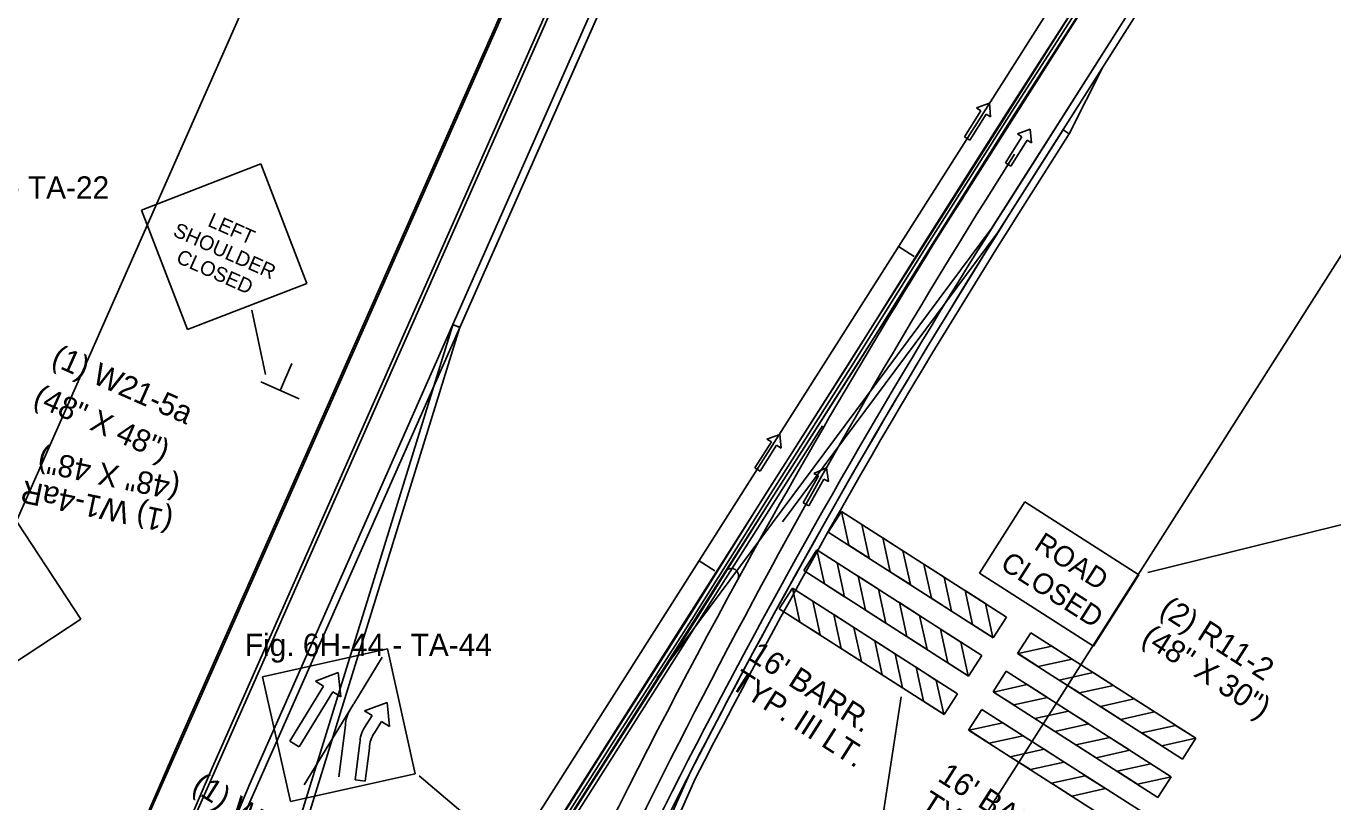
# Model space of a CAD drawing. Extents: x 659657 to 668193, y 633084 to 648639.
# Drawn here: x 661763.9 to 662115.3, y 641655.6 to 641864.1 of the extents above; entities that cross this region are included whole.
import ezdxf

# ---------------------------------------------------------------- set-up
doc = ezdxf.new("R2010")
doc.units = 0
for name, color, linetype in [('R_Border Prem', 7, 'Continuous'), ('R_Draft', 7, 'Continuous'), ('R_MOT_Stage 1A', 7, 'Continuous'), ('R_MOT_Stage 1A_Striping', 7, 'Continuous'), ('R_MOT_Stage 1B', 7, 'Continuous'), ('R_MOT_Stage 1B_Striping', 7, 'Continuous'), ('R_MOT_Stage 1C', 7, 'Continuous'), ('R_MOT_Stage 1C_Striping', 7, 'Continuous'), ('R_MOT_Stage 2', 7, 'Continuous'), ('R_MOT_Stage 2_Striping', 7, 'Continuous'), ('R_MOT_Stage 3_Striping_PPM', 7, 'Continuous'), ('R_MOT_Stage 4_Striping_PPM', 7, 'Continuous'), ('R_MOT_Stage 5_Striping_PPM', 7, 'Continuous'), ('S_EXISTING_ALIGNMENT', 7, 'Continuous'), ('T_Notes', 7, 'Continuous'), ('T_SIGNAL CONTROL CABINET', 7, 'Continuous'), ('TEMP_SIGNAL_HEAD_STAGE 2', 7, 'Continuous'), ('TEMP_SIGNAL_POLES_STAGE 3', 7, 'Continuous'), ('TEXT_TEMP_SIGNAL_POLES_STAGE 2', 7, 'Continuous')]:
    doc.layers.add(name, color=color, linetype=linetype)

msp = doc.modelspace()

# ---------------------------------------------------------------- linework, layer by layer
at = {"layer": 'R_Border Prem'}
msp.add_line((661686.79, 641562.92), (662861.91, 644217.67), dxfattribs=at)
at = {"layer": 'R_Draft'}
for p, q in [((661826.96, 641827.04), (661794.88, 641814.65)), ((661839.35, 641794.96), (661826.96, 641827.04)), ((661807.28, 641782.58), (661794.88, 641814.65)), ((661839.35, 641794.96), (661807.28, 641782.58)), ((661824.57, 641787.78), (661828.28, 641770.48)), ((661832.24, 641766.37), (661835.35, 641773.39)), ((661837.29, 641763.95), (661827, 641768.51))]:
    msp.add_line(p, q, dxfattribs=at)
at = {"layer": 'R_MOT_Stage 1A'}
for points in [[(661828.7, 641527.64), (661899.02, 641637.71), (661920.48, 641671.46), (661942.01, 641705.19), (661963.28, 641739.07), (661984.75, 641772.81), (662005.98, 641806.72), (662027.38, 641840.52), (662048.99, 641874.22)], [(661830.39, 641526.57), (661900.71, 641636.63), (661922.17, 641670.39), (661943.7, 641704.12), (661964.97, 641738), (661986.44, 641771.75), (662007.67, 641805.65), (662029.07, 641839.44), (662050.67, 641873.14)]]:
    msp.add_lwpolyline(points, dxfattribs=at)
at = {"layer": 'R_MOT_Stage 1A_Striping'}
msp.add_line((661764.81, 641437.19), (662110.96, 641981.8), dxfattribs=at)
for points in [[(661796.6, 641476.95), (661855.9, 641570.33), (661877.49, 641604), (661899.02, 641637.71), (661920.48, 641671.46), (661942.01, 641705.19), (661963.28, 641739.07), (661984.75, 641772.81), (662005.98, 641806.72), (662027.38, 641840.52), (662048.99, 641874.22)], [(662002.7, 641802.14), (661998.48, 641804.82)], [(661949.06, 641717.75), (661944.84, 641720.43)]]:
    msp.add_lwpolyline(points, dxfattribs=at)
at = {"layer": 'R_MOT_Stage 1B'}
for p, q in [((662029.07, 641814.74), (662096.24, 641920.42)), ((661828.79, 641527.59), (662056.76, 641886.27)), ((661830.47, 641526.51), (662058.45, 641885.2)), ((662044.4, 641835.14), (662053.45, 641853.09)), ((662029.07, 641814.74), (662042.72, 641836.21)), ((662044.4, 641835.14), (662042.72, 641836.21)), ((662044.4, 641835.14), (662030.76, 641813.66)), ((662044.4, 641835.14), (662030.76, 641813.66)), ((661933.9, 641644.44), (661942.13, 641662.91)), ((661943.82, 641661.83), (661935.6, 641643.36))]:
    msp.add_line(p, q, dxfattribs=at)
msp.add_lwpolyline([(661943.82, 641661.83), (661935.6, 641643.36), (661926.8, 641625.52), (661915.46, 641608.81)], dxfattribs=at)
for centre, radius, start, end in [((663629.94, 640797.24), 1896.86, 147.56037, 156.77389), ((663629.94, 640797.24), 1896.86, 147.56037, 152.84698), ((663629.94, 640797.24), 1894.86, 147.56037, 152.85257), ((663629.94, 640797.24), 1894.86, 147.56037, 152.85257), ((661953.48, 641716.32), 2, 331.2673, 147.5604)]:
    msp.add_arc(centre, radius, start, end, dxfattribs=at)
at = {"layer": 'R_MOT_Stage 1B_Striping'}
for p, q in [((661764.81, 641437.19), (662110.96, 641981.8)), ((662018.1, 641821.71), (662085.27, 641927.4)), ((662027.38, 641815.81), (662094.55, 641921.49)), ((661796.6, 641476.95), (662056.76, 641886.27))]:
    msp.add_line(p, q, dxfattribs=at)
for points in [[(662002.7, 641802.14), (661998.48, 641804.82)], [(661949.06, 641717.75), (661944.84, 641720.43)]]:
    msp.add_lwpolyline(points, dxfattribs=at)
for radius, start, end in [(1909.86, 147.56037, 151.26731), (1898.86, 147.56037, 156.77389), (1909.86, 151.26731, 156.77389)]:
    msp.add_arc((663629.94, 640797.24), radius, start, end, dxfattribs=at)
at = {"layer": 'R_MOT_Stage 1C'}
for p, q in [((662025.12, 641808.53), (662128.26, 641970.8)), ((661967.26, 641730.85), (662025.12, 641808.53))]:
    msp.add_line(p, q, dxfattribs=at)
at = {"layer": 'R_MOT_Stage 1C_Striping'}
for p, q in [((662023.47, 641809.66), (662126.57, 641971.87)), ((662025.03, 641832.62), (662085.27, 641927.4)), ((661933.56, 641688.95), (662023.47, 641809.66))]:
    msp.add_line(p, q, dxfattribs=at)
msp.add_arc((663641.52, 640805.21), 1915.36, 147.56037, 148.1682, dxfattribs=at)
at = {"layer": 'R_MOT_Stage 2'}
for points in [[(662645.5, 643511.36), (661880.49, 641783.11), (661878.66, 641783.92), (662643.67, 643512.17)], [(661825.01, 641610.82), (661878.63, 641783.81), (661880.54, 641783.21), (661826.92, 641610.23)]]:
    msp.add_lwpolyline(points, close=True, dxfattribs=at)
at = {"layer": 'R_MOT_Stage 2_Striping'}
for p, q in [((662653.91, 643589.66), (661803.9, 641669.37)), ((661813.96, 641664.92), (662663.97, 643585.2)), ((661824.02, 641660.47), (661878.66, 641783.92)), ((661803.9, 641669.37), (661763.88, 641577.73)), ((661774.4, 641573.08), (661813.96, 641664.92)), ((661824.02, 641660.47), (661785.37, 641568.22))]:
    msp.add_line(p, q, dxfattribs=at)
msp.add_lwpolyline([(661878.66, 641783.92), (662674.03, 643580.75)], dxfattribs=at)
at = {"layer": 'R_MOT_Stage 3_Striping_PPM'}
for p, q in [((661859, 641792.62), (662694.85, 643680.89)), ((661869.52, 641787.96), (662705.36, 643676.24)), ((661880.49, 641783.11), (662215.01, 642538.82)), ((661763.88, 641577.73), (661859, 641792.62)), ((661774.4, 641573.08), (661869.52, 641787.96)), ((661785.37, 641568.22), (661880.49, 641783.11))]:
    msp.add_line(p, q, dxfattribs=at)
at = {"layer": 'R_MOT_Stage 4_Striping_PPM'}
for p, q in [((661859, 641792.62), (662694.85, 643680.89)), ((661869.52, 641787.96), (662705.36, 643676.24)), ((661880.49, 641783.11), (662215.01, 642538.82)), ((661763.88, 641577.73), (661859, 641792.62)), ((661774.4, 641573.08), (661869.52, 641787.96)), ((661785.37, 641568.22), (661880.49, 641783.11))]:
    msp.add_line(p, q, dxfattribs=at)
at = {"layer": 'R_MOT_Stage 5_Striping_PPM'}
for p, q in [((661859, 641792.62), (662694.85, 643680.89)), ((661869.52, 641787.96), (662705.36, 643676.24)), ((661880.49, 641783.11), (662215.01, 642538.82)), ((661763.88, 641577.73), (661859, 641792.62)), ((661774.4, 641573.08), (661869.52, 641787.96)), ((661785.37, 641568.22), (661880.49, 641783.11))]:
    msp.add_line(p, q, dxfattribs=at)
at = {"layer": 'S_EXISTING_ALIGNMENT'}
for p, q in [((661764.81, 641437.19), (662110.96, 641981.8)), ((662006.37, 641627.8), (662163.94, 641875.56))]:
    msp.add_line(p, q, dxfattribs=at)
msp.add_arc((663641.52, 640805.21), 1909.86, 147.56037, 156.77389, dxfattribs=at)
at = {"layer": 'T_Notes'}
for p, q in [((661826.96, 641827.04), (661794.88, 641814.65)), ((661839.35, 641794.96), (661826.96, 641827.04)), ((661807.28, 641782.58), (661794.88, 641814.65)), ((661839.35, 641794.96), (661807.28, 641782.58)), ((661824.57, 641787.78), (661828.28, 641770.48)), ((661832.24, 641766.37), (661835.35, 641773.39)), ((661837.29, 641763.95), (661827, 641768.51)), ((661759.74, 641733.42), (661778.61, 641704.68)), ((661778.61, 641704.68), (661749.87, 641685.81))]:
    msp.add_line(p, q, dxfattribs=at)
at = {"layer": 'T_SIGNAL CONTROL CABINET'}
for p, q in [((662019.44, 641842.08), (662022.9, 641843.34)), ((662022.9, 641843.34), (662023.24, 641839.67)), ((662020.63, 641841.33), (662016.2, 641834.34)), ((662022.05, 641840.42), (662017.63, 641833.43)), ((662019.44, 641842.08), (662020.63, 641841.33)), ((662022.05, 641840.42), (662023.24, 641839.67)), ((662030.45, 641835.11), (662033.91, 641836.37)), ((662033.91, 641836.37), (662034.25, 641832.7)), ((662016.2, 641834.34), (662017.63, 641833.43)), ((662031.64, 641834.35), (662027.21, 641827.36)), ((662033.06, 641833.45), (662028.64, 641826.46)), ((662030.45, 641835.11), (662031.64, 641834.35)), ((662033.06, 641833.45), (662034.25, 641832.7)), ((662027.21, 641827.36), (662028.64, 641826.46)), ((661964.27, 641752.34), (661959.84, 641745.35)), ((661963.08, 641753.09), (661966.54, 641754.36)), ((661963.08, 641753.09), (661964.27, 641752.34)), ((661966.54, 641754.36), (661966.88, 641750.69)), ((661965.69, 641751.44), (661961.26, 641744.45)), ((661965.69, 641751.44), (661966.88, 641750.69)), ((661959.84, 641745.35), (661961.26, 641744.45)), ((661975.68, 641743.9), (661979.07, 641745.34)), ((661979.07, 641745.34), (661979.61, 641741.69)), ((661976.91, 641743.21), (661972.86, 641735.99)), ((661978.38, 641742.38), (661974.33, 641735.17)), ((661975.68, 641743.9), (661976.91, 641743.21)), ((661978.38, 641742.38), (661979.61, 641741.69)), ((661972.86, 641735.99), (661974.33, 641735.17))]:
    msp.add_line(p, q, dxfattribs=at)
for points in [[(661852.2, 641562.68), (661856.74, 641569.79), (661878.33, 641603.47), (661899.87, 641637.17), (661921.33, 641670.93), (661942.85, 641704.66), (661964.13, 641738.53), (661985.6, 641772.28), (662006.82, 641806.18), (662028.23, 641839.98), (662049.83, 641873.68)], [(661850.32, 641546.76), (661899.94, 641633.58), (661978.06, 641756.71)]]:
    msp.add_lwpolyline(points, dxfattribs=at)
at = {"layer": 'TEMP_SIGNAL_HEAD_STAGE 2'}
for p, q in [((662020.2, 641717.08), (662032.46, 641736.24)), ((662032.46, 641736.24), (662063.12, 641716.62)), ((662065.54, 641717.22), (662138.03, 641735.13)), ((661979.58, 641728.09), (661983.14, 641733.66)), ((662027.48, 641705.29), (661983.14, 641733.66)), ((662023.92, 641699.72), (661979.58, 641728.09)), ((661979.62, 641728.09), (661979.61, 641728.14)), ((661972.99, 641717.79), (661976.54, 641723.34)), ((661972.99, 641717.79), (661976.54, 641723.34)), ((662020.88, 641694.97), (661976.54, 641723.34)), ((662017.32, 641689.42), (661972.99, 641717.79)), ((662020.2, 641717.08), (662050.86, 641697.46)), ((662050.86, 641697.46), (662063.12, 641716.62)), ((661966.4, 641707.5), (661969.96, 641713.05)), ((662014.29, 641684.68), (661969.96, 641713.05)), ((662010.74, 641679.13), (661966.4, 641707.5)), ((662023.92, 641699.72), (662027.48, 641705.29)), ((662030.49, 641695.51), (662034.06, 641701.08)), ((662034.06, 641701.08), (662078.39, 641672.71)), ((662017.32, 641689.42), (662020.88, 641694.97)), ((662030.49, 641695.51), (662074.83, 641667.14)), ((662023.9, 641685.21), (662027.45, 641690.76)), ((662027.45, 641690.76), (662071.79, 641662.39)), ((662023.9, 641685.21), (662068.24, 641656.84)), ((661985.03, 641591.15), (661999.17, 641683.82)), ((662010.74, 641679.13), (662014.29, 641684.68)), ((662017.32, 641674.92), (662020.87, 641680.47)), ((662020.87, 641680.47), (662065.21, 641652.1)), ((662017.32, 641674.92), (662061.66, 641646.55)), ((662074.83, 641667.14), (662078.39, 641672.71)), ((662074.81, 641667.18), (662074.86, 641667.19)), ((662068.24, 641656.84), (662071.79, 641662.39)), ((662068.24, 641656.84), (662071.79, 641662.39))]:
    msp.add_line(p, q, dxfattribs=at)
for points in [[(661983.14, 641733.66), (661988.58, 641730.15), (661990.57, 641721.08), (661985.14, 641724.56)], [(661994.22, 641726.57), (661999.66, 641723.07), (662001.65, 641713.99), (661996.22, 641717.47)], [(661976.54, 641723.34), (661981.98, 641719.83), (661983.97, 641710.76), (661978.54, 641714.24)], [(662005.3, 641719.48), (662010.74, 641715.98), (662012.73, 641706.9), (662007.3, 641710.38)], [(661987.62, 641716.25), (661993.06, 641712.75), (661995.05, 641703.67), (661989.62, 641707.15)], [(661969.96, 641713.05), (661975.4, 641709.55), (661977.39, 641700.47), (661971.95, 641703.95)], [(662016.38, 641712.39), (662021.82, 641708.89), (662023.81, 641699.81), (662018.38, 641703.29)], [(661998.7, 641709.16), (662004.14, 641705.66), (662006.13, 641696.58), (662000.69, 641700.06)], [(661981.03, 641705.96), (661986.47, 641702.46), (661988.47, 641693.38), (661983.03, 641696.86)], [(662009.77, 641702.07), (662015.21, 641698.57), (662017.21, 641689.49), (662011.77, 641692.97)], [(661992.11, 641698.87), (661997.55, 641695.37), (661999.55, 641686.29), (661994.11, 641689.77)], [(662045.16, 641693.98), (662039.7, 641697.45), (662030.62, 641695.46), (662036.05, 641691.98)], [(662003.19, 641691.79), (662008.63, 641688.28), (662010.63, 641679.21), (662005.19, 641682.68)], [(662056.24, 641686.89), (662050.77, 641690.36), (662041.7, 641688.37), (662047.13, 641684.89)], [(662038.55, 641683.66), (662033.09, 641687.13), (662024.02, 641685.14), (662029.45, 641681.66)], [(662067.31, 641679.8), (662061.85, 641683.27), (662052.78, 641681.28), (662058.21, 641677.8)], [(662049.63, 641676.57), (662044.17, 641680.04), (662035.1, 641678.05), (662040.53, 641674.57)], [(662031.97, 641673.37), (662026.51, 641676.84), (662017.44, 641674.85), (662022.87, 641671.37)], [(662078.39, 641672.71), (662072.93, 641676.18), (662063.86, 641674.19), (662069.29, 641670.71)], [(662060.71, 641669.48), (662055.25, 641672.95), (662046.17, 641670.96), (662051.61, 641667.48)], [(662043.05, 641666.28), (662037.59, 641669.75), (662028.51, 641667.76), (662033.95, 641664.28)], [(662071.79, 641662.39), (662066.33, 641665.86), (662057.25, 641663.87), (662062.69, 641660.39)], [(662054.13, 641659.19), (662048.67, 641662.66), (662039.59, 641660.67), (662045.03, 641657.19)]]:
    msp.add_lwpolyline(points, close=True, dxfattribs=at)
at = {"layer": 'TEMP_SIGNAL_POLES_STAGE 3'}
msp.add_line((661764.81, 641437.19), (662110.96, 641981.8), dxfattribs=at)
for points in [[(662002.7, 641802.14), (661998.48, 641804.82)], [(661949.06, 641717.75), (661944.84, 641720.43)]]:
    msp.add_lwpolyline(points, dxfattribs=at)
at = {"layer": 'TEXT_TEMP_SIGNAL_POLES_STAGE 2'}
for p, q in [((661861.02, 641696.72), (661827.44, 641689.24)), ((661868.49, 641663.15), (661861.02, 641696.72)), ((661851.98, 641681.96), (661859.64, 641694.5)), ((661834.93, 641655.68), (661827.44, 641689.24)), ((661847.78, 641690.38), (661841.68, 641688.05)), ((661848.48, 641683.89), (661847.78, 641690.38)), ((661843.81, 641686.75), (661834.76, 641671.96)), ((661846.35, 641685.19), (661837.31, 641670.4)), ((661843.81, 641686.75), (661841.68, 641688.05)), ((661848.48, 641683.89), (661846.35, 641685.19)), ((661838.68, 641660.21), (661851.92, 641681.87)), ((661860.96, 641682.35), (661854.83, 641680.12)), ((661861.55, 641675.85), (661860.96, 641682.35)), ((661856.93, 641678.79), (661854.83, 641680.12)), ((661856.93, 641678.79), (661854.89, 641675.59)), ((661849.77, 641676.24), (661847.96, 641662.32)), ((661859.45, 641677.19), (661857.55, 641674.2)), ((661861.55, 641675.85), (661859.45, 641677.19)), ((661834.76, 641671.96), (661837.31, 641670.4)), ((661853.64, 641671.46), (661852.34, 641661.55)), ((661856.19, 641670.09), (661855.03, 641661.2)), ((661868.49, 641663.15), (661834.93, 641655.68)), ((661852.34, 641661.55), (661855.03, 641661.2)), ((661869.58, 641662.58), (661902.43, 641634.85))]:
    msp.add_line(p, q, dxfattribs=at)
for centre, radius, start, end in [((661857.21, 641676.23), 7.43, 146.2329, 179.9908), ((661861.07, 641671.46), 7.43, 146.2329, 179.9908), ((661863.65, 641669.9), 7.47, 144.8282, 178.5861)]:
    msp.add_arc(centre, radius, start, end, dxfattribs=at)

# ---------------------------------------------------------------- texts
at = {"layer": 'R_Draft'}
for s, height, rotation, p in [('LEFT', 3.94, 336.1224, (661812.45, 641810.46)), ('SHOULDER', 3.94, 336.122, (661803.11, 641807.82)), ('CLOSED', 3.94, 336.122, (661803.94, 641800.67)), ('(1) W21-5a', 6, 336.1234, (661770.31, 641773.21)), ('(48" X 48")', 6, 336.1234, (661765.4, 641762.54))]:
    msp.add_text(s, height=height, rotation=rotation, dxfattribs=at).set_placement(p)
at = {"layer": 'T_Notes'}
for s, height, rotation, p in [('LEFT', 3.94, 336.1224, (661812.45, 641810.46)), ('SHOULDER', 3.94, 336.122, (661803.11, 641807.82)), ('CLOSED', 3.94, 336.122, (661803.94, 641800.67)), ('(1) W21-5a', 6, 336.1234, (661770.31, 641773.21)), ('(48" X 48")', 6, 336.1234, (661765.4, 641762.54)), ('(48" X 48")', 6, 168.2802, (661805.57, 641742.44)), ('(1) W1-4aR', 6, 168.2802, (661803.74, 641733.63))]:
    msp.add_text(s, height=height, rotation=rotation, dxfattribs=at).set_placement(p)
at = {"layer": 'T_SIGNAL CONTROL CABINET'}
for s, p in [('Fig. 6H-22 - TA-22', (661719.77, 641817.71)), ('Fig. 6H-44 - TA-44', (661822.69, 641694.81))]:
    msp.add_text(s, height=6, dxfattribs=at).set_placement(p)
at = {"layer": 'TEMP_SIGNAL_HEAD_STAGE 2'}
for s, height, p in [('ROAD', 5.51, (662034.6, 641723.7)), ('CLOSED', 5.537, (662025.51, 641718.56)), ('(2) R11-2', 6, (662068.31, 641706.17)), ('(48" X 30")', 6, (662063.46, 641698.59)), ("16' BARR.", 6, (661957.78, 641694.02)), ('TYP. III LT.', 6, (661952.93, 641686.44)), ("16' BARR.", 6, (662008.7, 641661.45)), ('TYP. III RT.', 6, (662003.84, 641653.87))]:
    msp.add_text(s, height=height, rotation=327.3866, dxfattribs=at).set_placement(p)
at = {"layer": 'TEXT_TEMP_SIGNAL_POLES_STAGE 2'}
msp.add_text('(1) W4-3R', height=6, rotation=327.5579, dxfattribs=at).set_placement((661808.13, 641658.86))

doc.saveas('drawing.dxf')
